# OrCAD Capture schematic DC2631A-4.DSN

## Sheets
1 PAGE3: size A
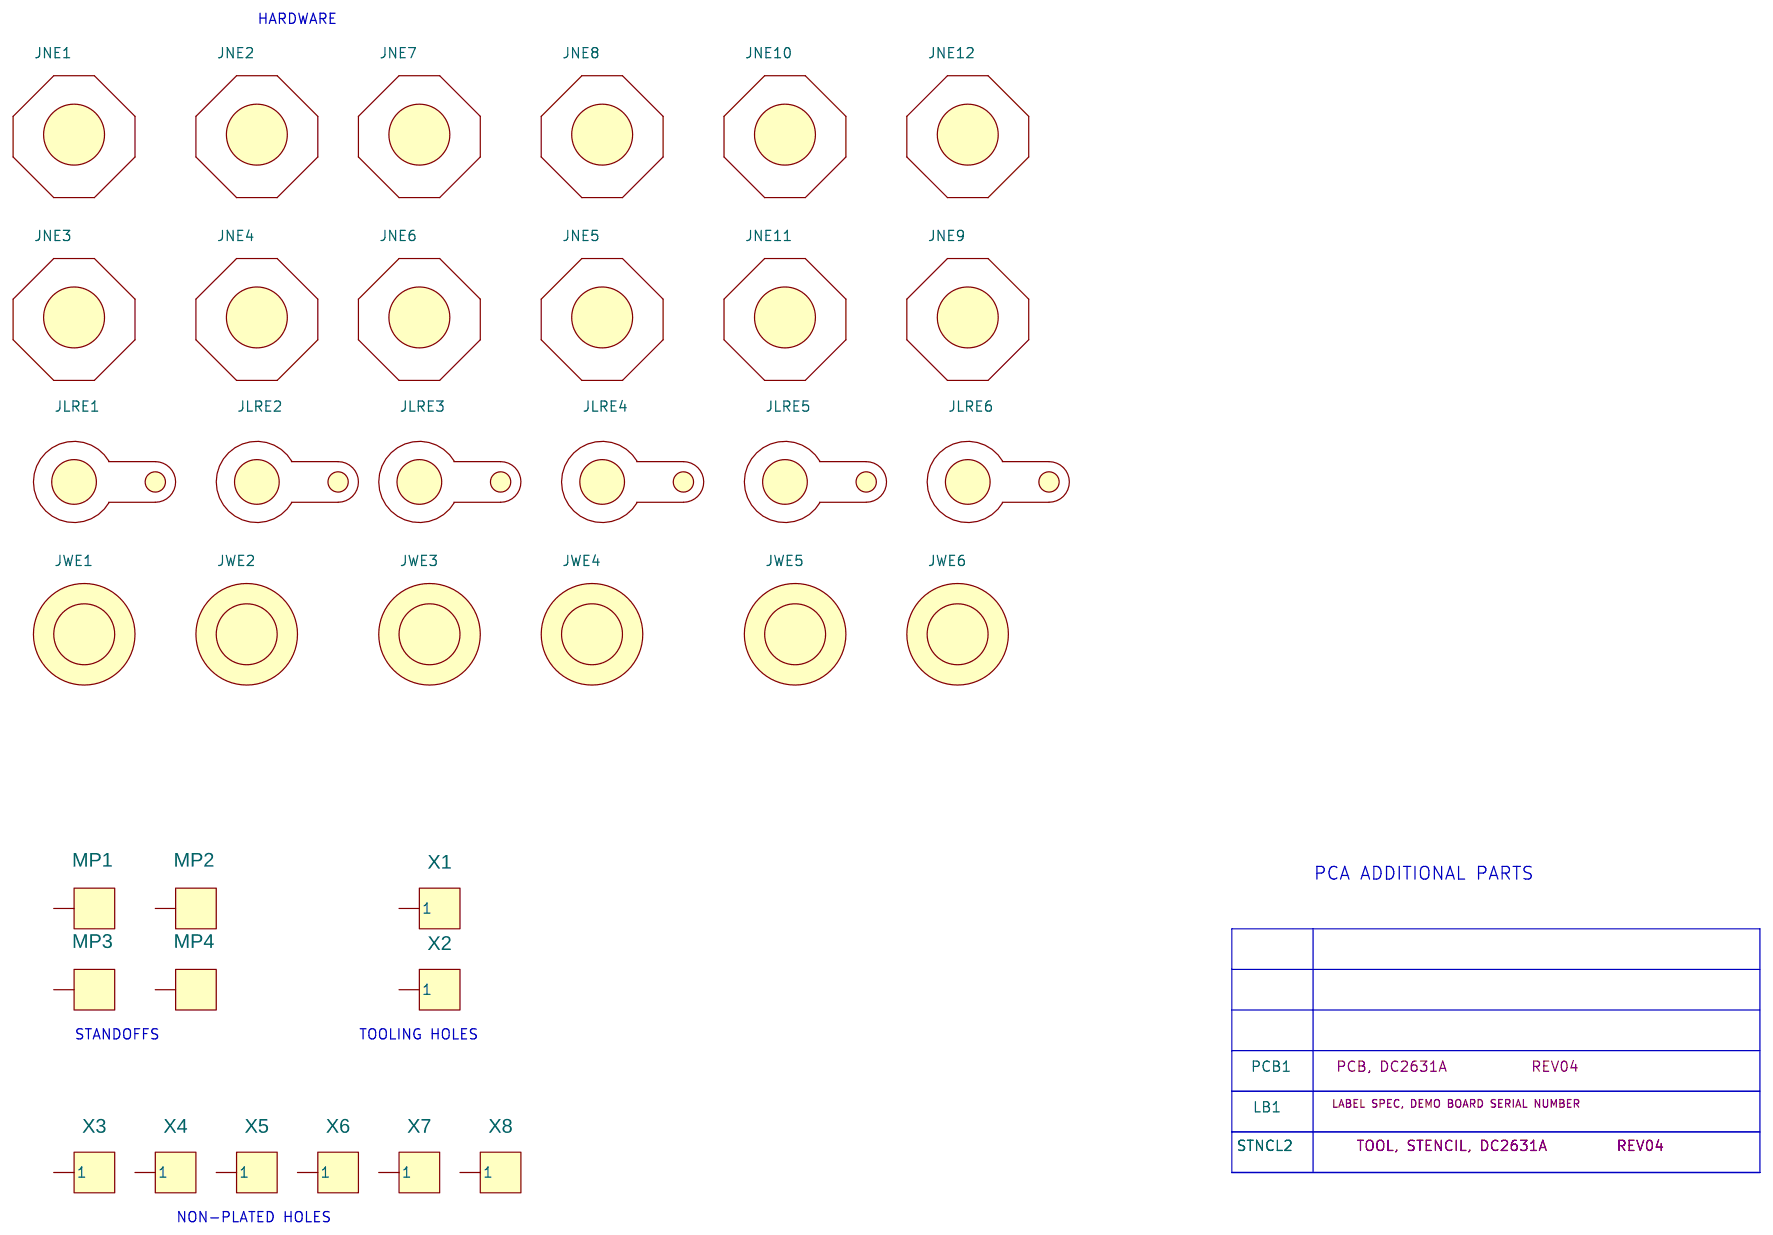
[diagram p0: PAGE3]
2 PAGE1: size Custom; company: ANALOG DEVICES; note: DEMO BOARD BILL OF MATERIALS; note: HIGH EFFICIENCY 6  PHASE STEP-DOWN CONVERTER
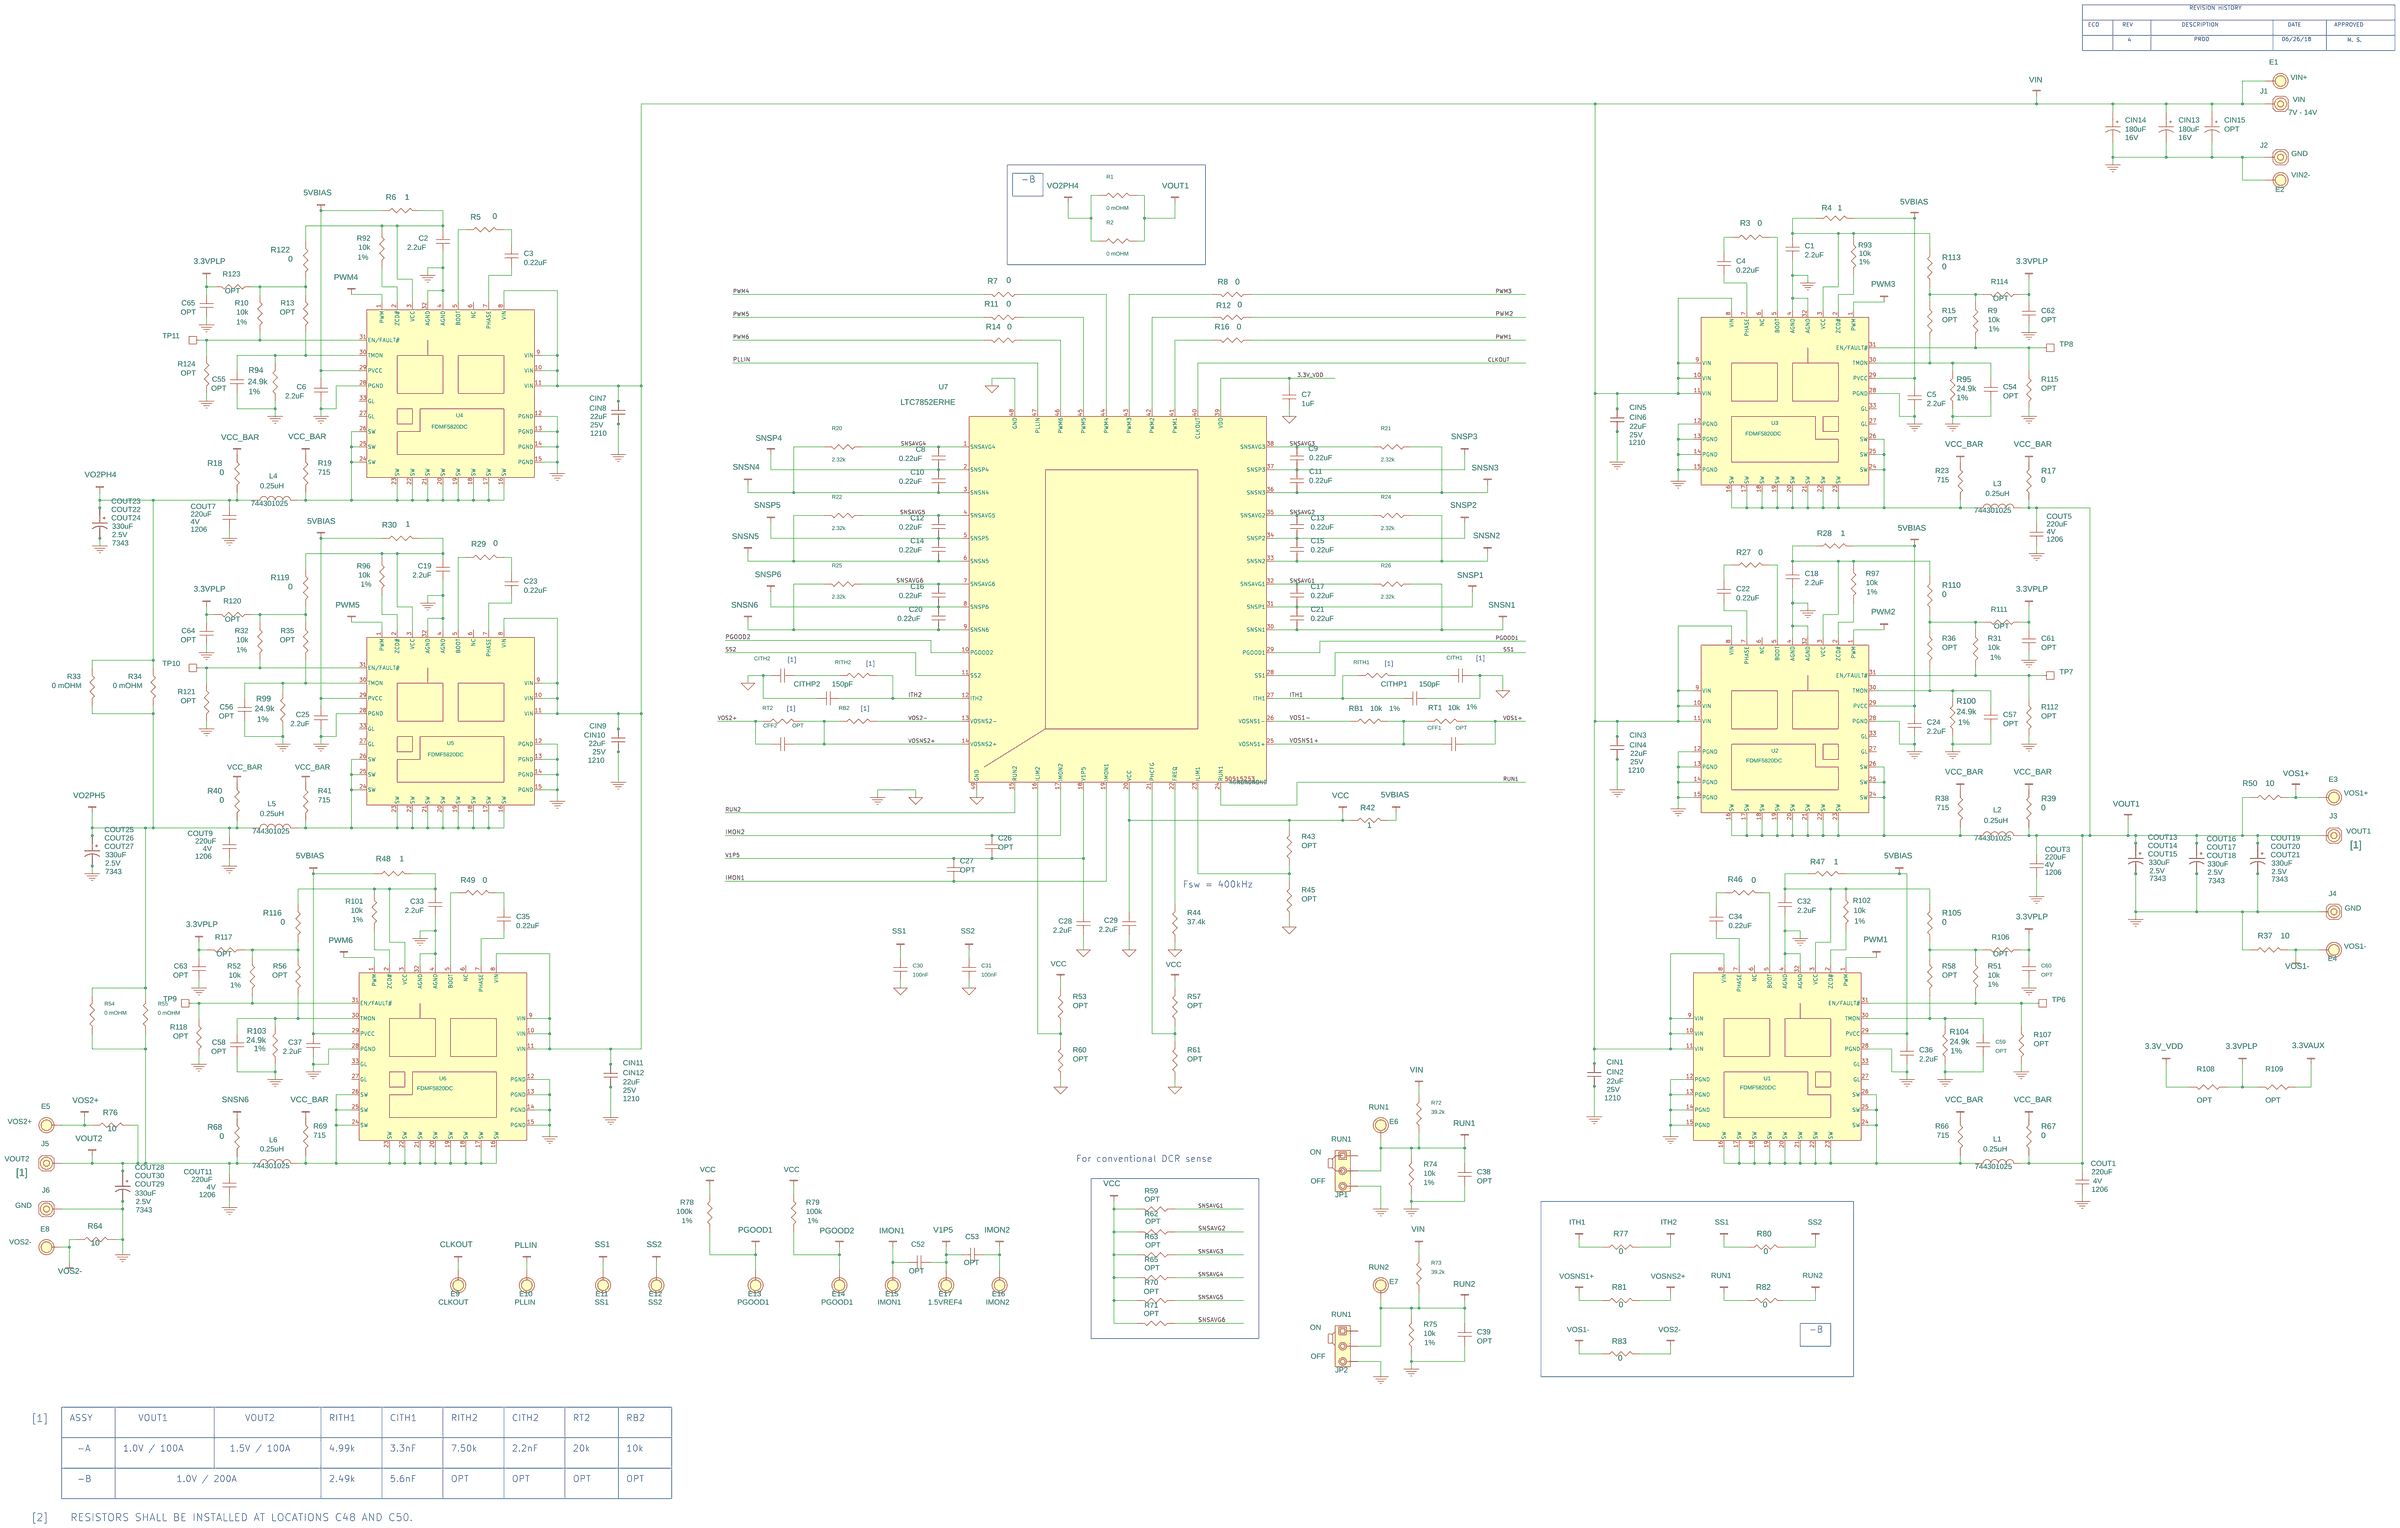
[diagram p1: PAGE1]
3 PAGE2: size Custom; company: ANALOG DEVICES; note: DEMO BOARD BILL OF MATERIALS; note: HIGH EFFICIENCY 6  PHASE STEP-DOWN CONVERTER
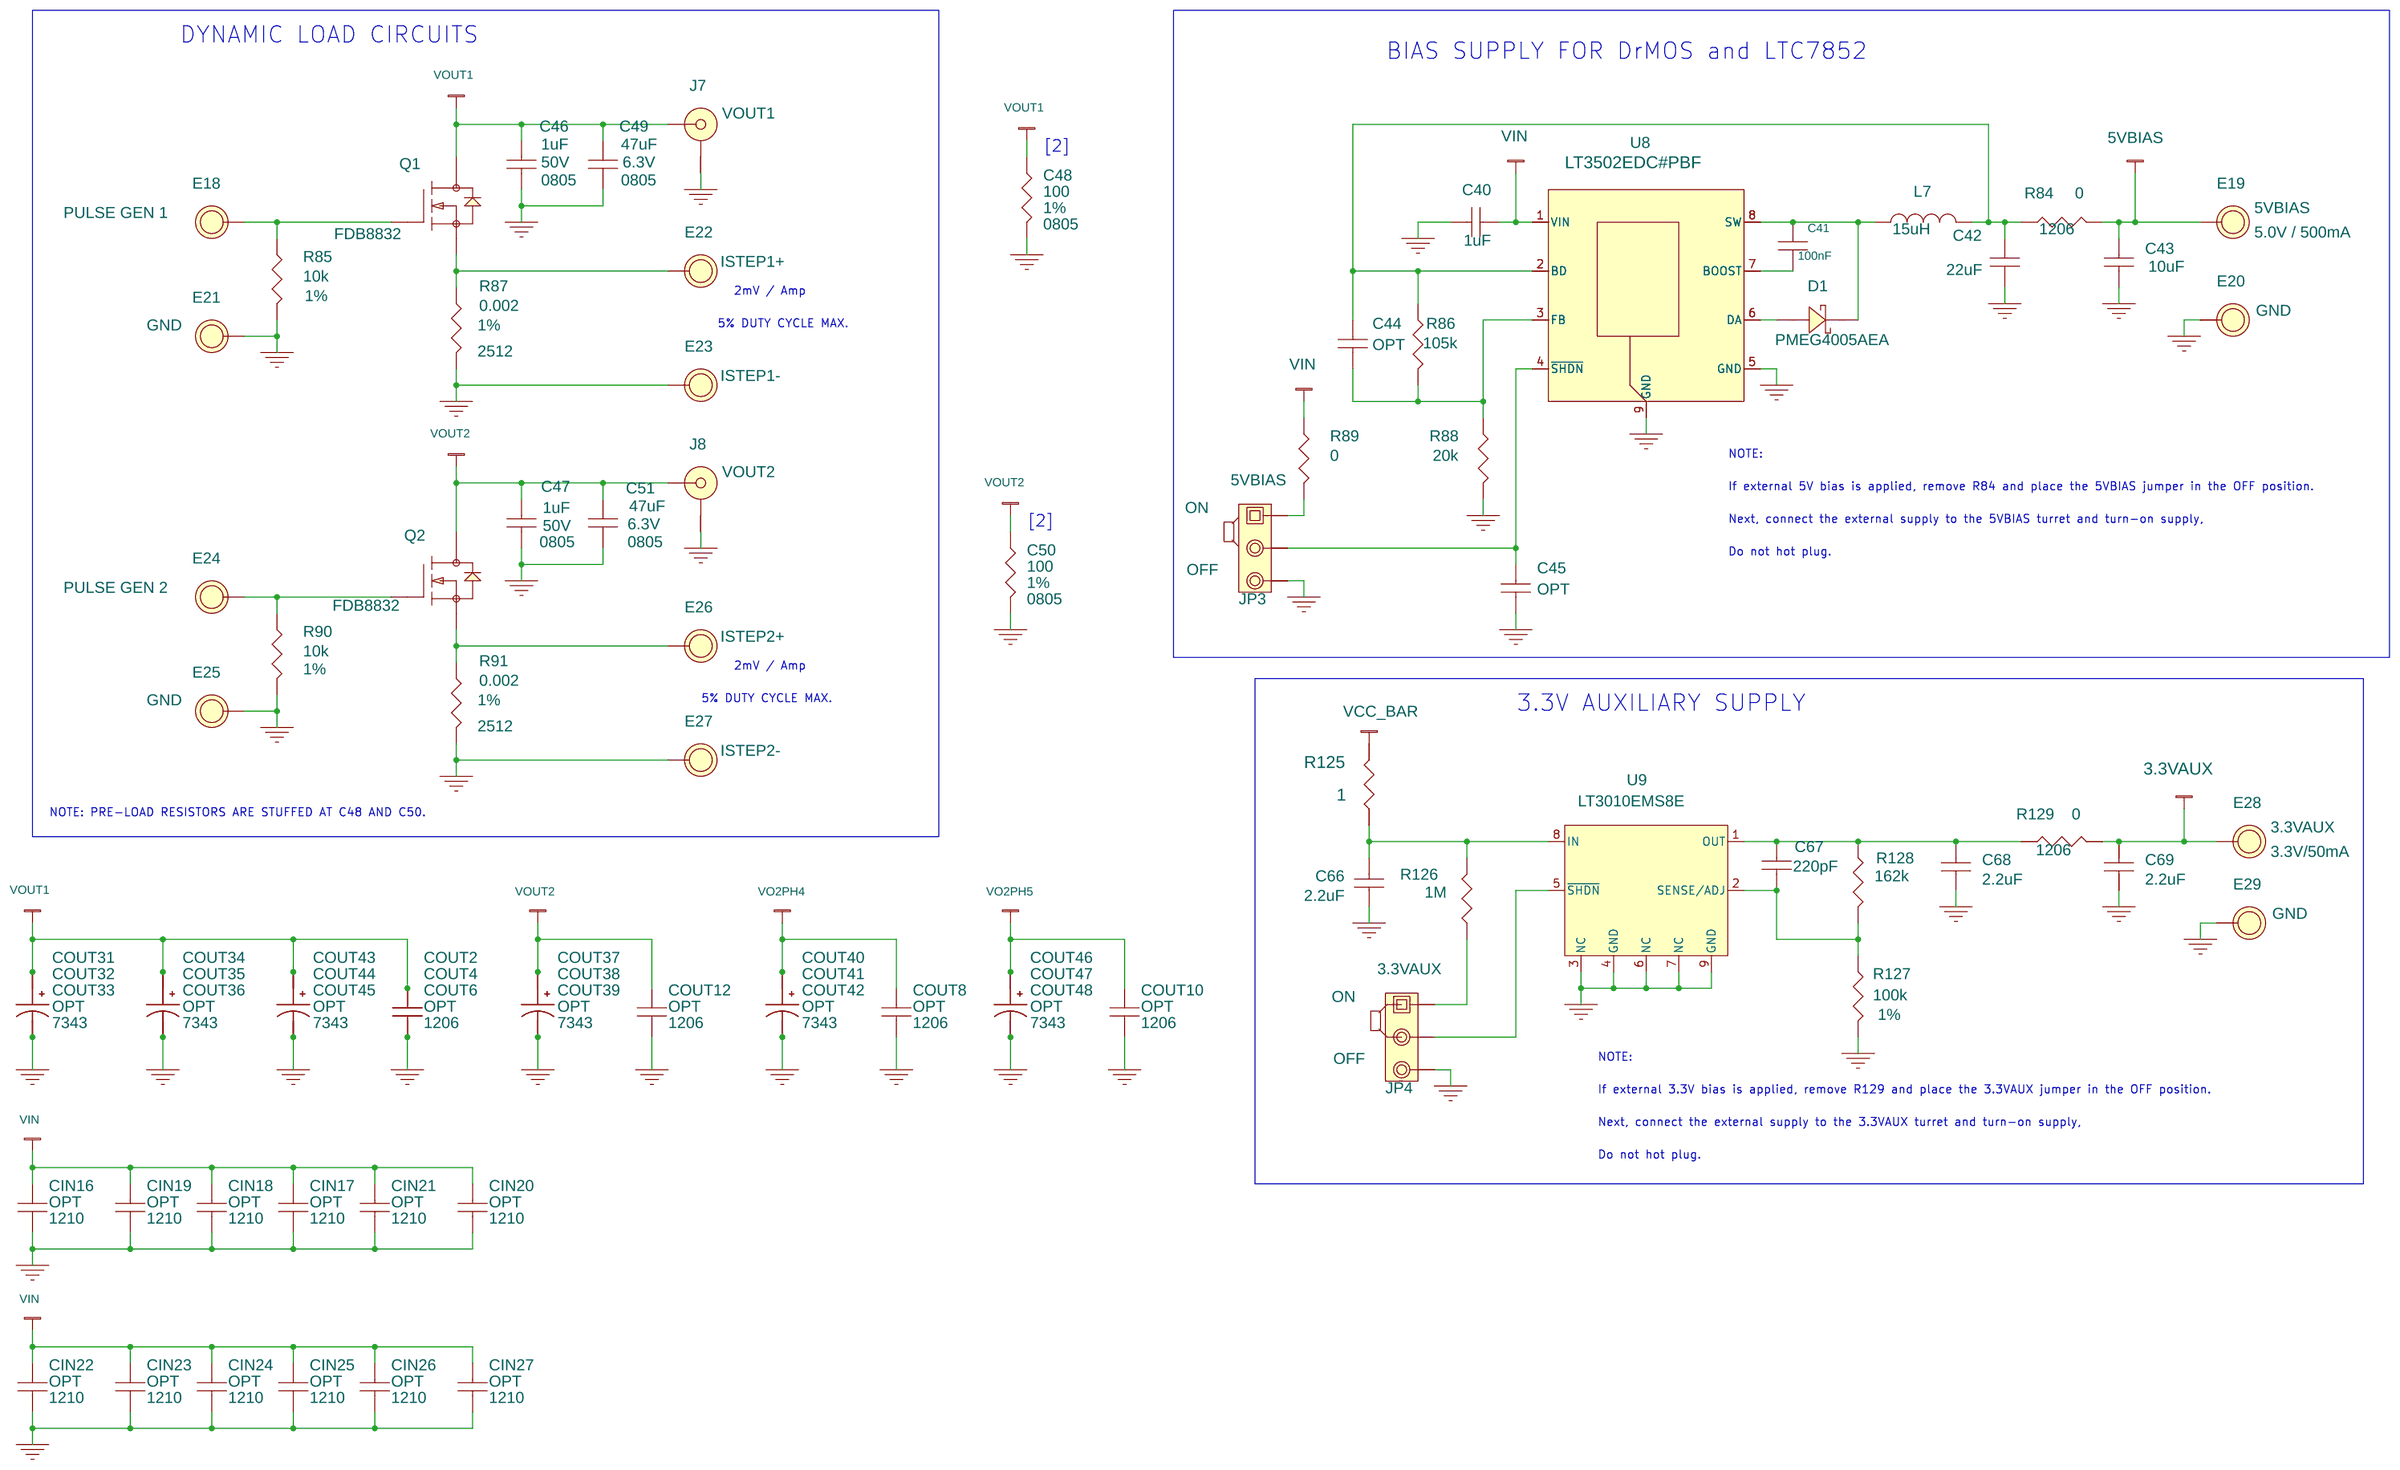
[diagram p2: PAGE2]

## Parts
sheet PAGE1
C1  2.2uF  [CC0603N]
C2  2.2uF  [CC0603N]
C3  0.22uF  [CC0603N]
C4  0.22uF  [CC0603N]
C5  2.2uF  [CC0603N]
C6  2.2uF  [CC0603N]
C7  1uF  [CC0603N]
C8  0.22uF  [CC0603N]
C9  0.22uF  [CC0603N]
C10  0.22uF  [CC0603N]
C11  0.22uF  [CC0603N]
C12  0.22uF  [CC0603N]
C13  0.22uF  [CC0603N]
C14  0.22uF  [CC0603N]
C15  0.22uF  [CC0603N]
C16  0.22uF  [CC0603N]
C17  0.22uF  [CC0603N]
C18  2.2uF  [CC0603N]
C19  2.2uF  [CC0603N]
C20  0.22uF  [CC0603N]
C21  0.22uF  [CC0603N]
C22  0.22uF  [CC0603N]
C23  0.22uF  [CC0603N]
C24  2.2uF  [CC0603N]
C25  2.2uF  [CC0603N]
C26  OPT  [CC0603N]
C27  OPT  [CC0603N]
C28  2.2uF  [CC0603N]
C29  2.2uF  [CC0603N]
C30  100nF  [CC0603N]
C31  100nF  [CC0603N]
C32  2.2uF  [CC0603N]
C33  2.2uF  [CC0603N]
C34  0.22uF  [CC0603N]
C35  0.22uF  [CC0603N]
C36  2.2uF  [CC0603N]
C37  2.2uF  [CC0603N]
C38  OPT  [CC0603N]
C39  OPT  [CC0603N]
C52  OPT  [CC0603N]
C53  OPT  [CC0603N]
C54  OPT  [CC0603N]
C55  OPT  [CC0603N]
C56  OPT  [CC0603N]
C57  OPT  [CC0603N]
C58  OPT  [CC0603N]
C59  OPT  [CC0603N]
C60  OPT  [CC0603N]
C61  OPT  [CC0603N]
C62  OPT  [CC0603N]
C63  OPT  [CC0603N]
C64  OPT  [CC0603N]
C65  OPT  [CC0603N]
CFF1  OPT  [CC0603N]
CFF2  OPT  [CC0603N]
CIN1  22uF  [CC1210N]
CIN2  22uF  [CC1210N]
CIN3  22uF  [CC1210N]
CIN4  22uF  [CC1210N]
CIN5  22uF  [CC1210N]
CIN6  22uF  [CC1210N]
CIN7  22uF  [CC1210N]
CIN8  22uF  [CC1210N]
CIN9  22uF  [CC1210N]
CIN10  22uF  [CC1210N]
CIN11  22uF  [CC1210N]
CIN12  22uF  [CC1210N]
CIN13  180uF  [CAP\SANYO\SVP\F8\10.3X10.3]
CIN14  180uF  [CAP\SANYO\SVP\F8\10.3X10.3]
CIN15  OPT  [CAP\SANYO\SVP\F8\10.3X10.3]
CITH1  3300pF  [CC0603N]
CITH2  2200pF  [CC0603N]
CITHP1  150pF  [CC0603N]
CITHP2  150pF  [CC0603N]
COUT1  220uF  [CC1206N]
COUT3  220uF  [CC1206N]
COUT5  220uF  [CC1206N]
COUT7  220uF  [CC1206N]
COUT9  220uF  [CC1206N]
COUT11  220uF  [CC1206N]
COUT13  330uF  [CAPMP7343N]
COUT14  330uF  [CAPMP7343N]
COUT15  330uF  [CAPMP7343N]
COUT16  330uF  [CAPMP7343N]
COUT17  330uF  [CAPMP7343N]
COUT18  330uF  [CAPMP7343N]
COUT19  330uF  [CAPMP7343N]
COUT20  330uF  [CAPMP7343N]
COUT21  330uF  [CAPMP7343N]
COUT22  330uF  [CAPMP7343N]
COUT23  330uF  [CAPMP7343N]
COUT24  330uF  [CAPMP7343N]
COUT25  330uF  [CAPMP7343N]
COUT26  330uF  [CAPMP7343N]
COUT27  330uF  [CAPMP7343N]
COUT28  330uF  [CAPMP7343N]
COUT29  330uF  [CAPMP7343N]
COUT30  330uF  [CAPMP7343N]
E1  TEST POINT  [MM/2501]
E2  TEST POINT  [MM/2501]
E3  TEST POINT  [MM/2501]
E4  TEST POINT  [MM/2501]
E5  TEST POINT  [MM/2501]
E6  TEST POINT  [MM/2501]
E7  TEST POINT  [MM/2501]
E8  TEST POINT  [MM/2501]
E9  TEST POINT  [MM/2501]
E10  TEST POINT  [MM/2501]
E11  TEST POINT  [MM/2501]
E12  TEST POINT  [MM/2501]
E13  TEST POINT  [MM/2501]
E14  TEST POINT  [MM/2501]
E15  TEST POINT  [MM/2501]
E16  TEST POINT  [MM/2501]
E17  TEST POINT  [MM/2501]
J1  STUD, FASTENER, #10-32  [PENN-KFH-032]
J2  STUD, FASTENER, #10-32  [PENN-KFH-032]
J3  STUD, FASTENER, #10-32  [PENN-KFH-032]
J4  STUD, FASTENER, #10-32  [PENN-KFH-032]
J5  STUD, FASTENER, #10-32  [PENN-KFH-032]
J6  STUD, FASTENER, #10-32  [PENN-KFH-032]
JP1  HDR  [HD1X3-079]
JP2  HDR  [HD1X3-079]
L1  0.25uH  [IND\WURTH\7443010XX]
L2  0.25uH  [IND\WURTH\7443010XX]
L3  0.25uH  [IND\WURTH\7443010XX]
L4  0.25uH  [IND\WURTH\7443010XX]
L5  0.25uH  [IND\WURTH\7443010XX]
L6  0.25uH  [IND\WURTH\7443010XX]
R1  0 mOHM  [RN6083_2010]
R2  0 mOHM  [RN6083_2010]
R3  0  [CR0603N]
R4  1  [CR0603N]
R5  0  [CR0603N]
R6  1  [CR0603N]
R7  0  [CR0603N]
R8  0  [CR0603N]
R9  10k  [CR0603N]
R10  10k  [CR0603N]
R11  0  [CR0603N]
R12  0  [CR0603N]
R13  OPT  [CR0603N]
R14  0  [CR0603N]
R15  OPT  [CR0603N]
R16  0  [CR0603N]
R17  0  [CR0603N]
R18  0  [CR0603N]
R19  715  [CR0603N]
R20  2.32k  [CR0603N]
R21  2.32k  [CR0603N]
R22  2.32k  [CR0603N]
R23  715  [CR0603N]
R24  2.32k  [CR0603N]
R25  2.32k  [CR0603N]
R26  2.32k  [CR0603N]
R27  0  [CR0603N]
R28  1  [CR0603N]
R29  0  [CR0603N]
R30  1  [CR0603N]
R31  10k  [CR0603N]
R32  10k  [CR0603N]
R33  0 mOHM  [RN6083_2010]
R34  0 mOHM  [RN6083_2010]
R35  OPT  [CR0603N]
R36  OPT  [CR0603N]
R37  10  [CR0603N]
R38  715  [CR0603N]
R39  0  [CR0603N]
R40  0  [CR0603N]
R41  715  [CR0603N]
R42  1  [CR0603N]
R43  OPT  [CR0603N]
R44  37.4k  [CR0603N]
R45  OPT  [CR0603N]
R46  0  [CR0603N]
R47  1  [CR0603N]
R48  1  [CR0603N]
R49  0  [CR0603N]
R50  10  [CR0603N]
R51  10k  [CR0603N]
R52  10k  [CR0603N]
R53  OPT  [CR0603N]
R54  0 mOHM  [RN6083_2010]
R55  0 mOHM  [RN6083_2010]
R56  OPT  [CR0603N]
R57  OPT  [CR0603N]
R58  OPT  [CR0603N]
R59  OPT  [CR0603N]
R60  OPT  [CR0603N]
R61  OPT  [CR0603N]
R62  OPT  [CR0603N]
R63  OPT  [CR0603N]
R64  10  [CR0603N]
R65  OPT  [CR0603N]
R66  715  [CR0603N]
R67  0  [CR0603N]
R68  0  [CR0603N]
R69  715  [CR0603N]
R70  OPT  [CR0603N]
R71  OPT  [CR0603N]
R72  39.2k  [CR0603N]
R73  39.2k  [CR0603N]
R74  10k  [CR0603N]
R75  10k  [CR0603N]
R76  10  [CR0603N]
R77  0  [CR0603N]
R78  100k  [CR0603N]
R79  100k  [CR0603N]
R80  0  [CR0603N]
R81  0  [CR0603N]
R82  0  [CR0603N]
R83  0  [CR0603N]
R92  10k  [CR0603N]
R93  10k  [CR0603N]
R94  24.9k  [CR0603N]
R95  24.9k  [CR0603N]
R96  10k  [CR0603N]
R97  10k  [CR0603N]
R99  24.9k  [CR0603N]
R100  24.9k  [CR0603N]
R101  10k  [CR0603N]
R102  10k  [CR0603N]
R103  24.9k  [CR0603N]
R104  24.9k  [CR0603N]
R105  0  [CR0603N]
R106  OPT  [CR0603N]
R107  OPT  [CR0603N]
R108  OPT  [CR0603N]
R109  OPT  [CR0603N]
R110  0  [CR0603N]
R111  OPT  [CR0603N]
R112  OPT  [CR0603N]
R113  0  [CR0603N]
R114  OPT  [CR0603N]
R115  OPT  [CR0603N]
R116  0  [CR0603N]
R117  OPT  [CR0603N]
R118  OPT  [CR0603N]
R119  0  [CR0603N]
R120  OPT  [CR0603N]
R121  OPT  [CR0603N]
R122  0  [CR0603N]
R123  OPT  [CR0603N]
R124  OPT  [CR0603N]
RB1  10k  [CR0603N]
RB2  10k  [CR0603N]
RITH1  4.99k  [CR0603N]
RITH2  7.5k  [CR0603N]
RT1  10k  [CR0603N]
RT2  20k  [CR0603N]
TP6  CLKOUT34  [TEST-PADS]
TP7  CLKOUT34  [TEST-PADS]
TP8  CLKOUT34  [TEST-PADS]
TP9  CLKOUT34  [TEST-PADS]
TP10  CLKOUT34  [TEST-PADS]
TP11  CLKOUT34  [TEST-PADS]
U1  FDMF5820DC  [fAIRCHILD-FDMF5820DC]
U2  FDMF5820DC  [fAIRCHILD-FDMF5820DC]
U3  FDMF5820DC  [fAIRCHILD-FDMF5820DC]
U4  FDMF5820DC  [fAIRCHILD-FDMF5820DC]
U5  FDMF5820DC  [fAIRCHILD-FDMF5820DC]
U6  FDMF5820DC  [fAIRCHILD-FDMF5820DC]
U7  LTC7852ERHE  [LTC-RHE-48-1527]
XJP1  SHUNT
XJP2  SHUNT
sheet PAGE2
C40  1uF  [CC0805N]
C41  100nF  [CC0603N]
C42  22uF  [CC0805N]
C43  10uF  [CC0805N]
C44  OPT  [CC0603N]
C45  OPT  [CC0603N]
C46  1uF  [CC0805N]
C47  1uF  [CC0805N]
C48  100  [CR0805N]
C49  47uF  [CC0805N]
C50  100  [CR0805N]
C51  47uF  [CC0805N]
C66  2.2uF  [CC0603N]
C67  220pF  [CC0603N]
C68  2.2uF  [CC0603N]
C69  2.2uF  [CC0603N]
CIN16  OPT  [CC1210N]
CIN17  OPT  [CC1210N]
CIN18  OPT  [CC1210N]
CIN19  OPT  [CC1210N]
CIN20  OPT  [CC1210N]
CIN21  OPT  [CC1210N]
CIN22  OPT  [CC1210N]
CIN23  OPT  [CC1210N]
CIN24  OPT  [CC1210N]
CIN25  OPT  [CC1210N]
CIN26  OPT  [CC1210N]
CIN27  OPT  [CC1210N]
COUT2  OPT  [CC1206N]
COUT4  OPT  [CC1206N]
COUT6  OPT  [CC1206N]
COUT8  OPT  [CC1206N]
COUT10  OPT  [CC1206N]
COUT12  OPT  [CC1206N]
COUT31  OPT  [CAPMP7343N]
COUT32  OPT  [CAPMP7343N]
COUT33  OPT  [CAPMP7343N]
COUT34  OPT  [CAPMP7343N]
COUT35  OPT  [CAPMP7343N]
COUT36  OPT  [CAPMP7343N]
COUT37  OPT  [CAPMP7343N]
COUT38  OPT  [CAPMP7343N]
COUT39  OPT  [CAPMP7343N]
COUT40  OPT  [CAPMP7343N]
COUT41  OPT  [CAPMP7343N]
COUT42  OPT  [CAPMP7343N]
COUT43  OPT  [CAPMP7343N]
COUT44  OPT  [CAPMP7343N]
COUT45  OPT  [CAPMP7343N]
COUT46  OPT  [CAPMP7343N]
COUT47  OPT  [CAPMP7343N]
COUT48  OPT  [CAPMP7343N]
D1  PMEG4005AEA  [SOD323]
E18  TEST POINT  [MM/2501]
E19  TEST POINT  [MM/2501]
E20  TEST POINT  [MM/2501]
E21  TEST POINT  [MM/2501]
E22  TEST POINT  [MM/2501]
E23  TEST POINT  [MM/2501]
E24  TEST POINT  [MM/2501]
E25  TEST POINT  [MM/2501]
E26  TEST POINT  [MM/2501]
E27  TEST POINT  [MM/2501]
E28  TEST POINT  [MM/2501]
E29  TEST POINT  [MM/2501]
J7  RF, BNC  [BNC5]
J8  RF, BNC  [BNC5]
JP3  HDR  [HD1X3-079]
JP4  HDR  [HD1X3-079]
L7  15uH  [IND\EATON\MP140-V2]
Q1  FDB8832  [TO-263AB]
Q2  FDB8832  [TO-263AB]
R84  0  [CR1206N]
R85  10k  [CR0603N]
R86  105k  [CR0603N]
R87  0.002  [CR2512N]
R88  20k  [CR0603N]
R89  0  [CR0603N]
R90  10k  [CR0603N]
R91  0.002  [CR2512N]
R125  1  [CR0603N]
R126  1M  [CR0603N]
R127  100k  [CR0603N]
R128  162k  [CR0603N]
R129  0  [CR1206N]
U8  LT3502EDC#PBF  [LTC-DC8-8-1719]
U9  LT3010EMS8E  [LTC-MS8E-8-1662]
XJP3  SHUNT
XJP4  SHUNT
sheet PAGE3
JLRE1  Lug_Ring
JLRE2  Lug_Ring
JLRE3  Lug_Ring
JLRE4  Lug_Ring
JLRE5  Lug_Ring
JLRE6  Lug_Ring
JNE1  NUT
JNE2  NUT
JNE3  NUT
JNE4  NUT
JNE5  NUT
JNE6  NUT
JNE7  NUT
JNE8  NUT
JNE9  NUT
JNE10  NUT
JNE11  NUT
JNE12  NUT
JWE1  Washer
JWE2  Washer
JWE3  Washer
JWE4  Washer
JWE5  Washer
JWE6  Washer
LB1  LABEL  [895-0154_REV01]
MP1  STANDOFF  [KEYSTONE_8829-8834]
MP2  STANDOFF  [KEYSTONE_8829-8834]
MP3  STANDOFF  [KEYSTONE_8829-8834]
MP4  STANDOFF  [KEYSTONE_8829-8834]
PCB1  PCB, DC2631A
STNCL1  TOOL, STENCIL, 700-DC2631A
STNCL2  TOOL, STENCIL, 700-DC2631A
X1  CON1  [TOOL\ALGNHL\70]
X2  CON1  [TOOL\ALGNHL\70]
X3  CON1  [RP40\20]
X4  CON1  [RP40\20]
X5  CON1  [RP40\20]
X6  CON1  [RP40\20]
X7  CON1  [RP40\20]
X8  CON1  [RP40\20]

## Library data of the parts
C1 C2 C5 C6 C18 C19 C24 C25 C28 C29 C32 C33 C36 C37 C66 C68 C69 = CAP: CAP.,2.2uF,X5R,16V,10%,0603; CLASS: DISCRETE; Dielectric Type: X5R; FPLIST: CC0603N,CC0603L,CC0603M; Manufacturer: KEMET; Manufacturer PN: C0603C225K4PAC7867; PART_NUMBER: 150-0552; Package Size: 0603; Rated Voltage: 16V; Tolerance: 10%
C3 C4 C8-C17 C20-C23 C34 C35 = CAP: CAP.,0.22uF,X5R,25V,10%,0603; CLASS: DISCRETE; Dielectric Type: X5R; FPLIST: CC0603N,CC0603L,CC0603M; Manufacturer: AVX; Manufacturer PN: 06033D224KAT2A; PART_NUMBER: 150-3369; Package Size: 0603; Rated Voltage: 25V; Tolerance: 10%
C7 = CAP: CAP.,1uF,X5R,25V,20%,0603; CLASS: DISCRETE; Dielectric Type: X5R; FPLIST: CC0603N,CC0603L,CC0603M; Manufacturer: AVX; Manufacturer PN: 06033D105MAT2A; PART_NUMBER: 150-0187; Package Size: 0603; Rated Voltage: 25V; Tolerance: 20%
C26 C27 C38 C39 C52-C65 = CAP: CAP., OPTION, 0603; CLASS: DISCRETE; FPLIST: CC0603N,CC0603L,CC0603M; PART_NUMBER: 150-3038; Package Size: 0603; Package Type: SMD
C30 C31 C41 = CAP: CAP.,0.1uF,X7R,16V,5%,0603; CLASS: DISCRETE; Dielectric Type: X7R; FPLIST: CC0603N,CC0603L,CC0603M; Manufacturer: AVX; Manufacturer PN: 0603YC104JAT2A; PART_NUMBER: 150-3212; Package Size: 0603; Rated Voltage: 16V; Tolerance: 5%
C44 C45 CFF1 CFF2 = CAP: CAP., OPTION, 0603; CLASS: DISCRETE; FPLIST: CC0603N,CC0603L,CC0603M; PART_NUMBER: 150-3038; Package Size: 0603; Package Type: SMD; Part Number: OPTION
CIN1-CIN12 = CAP: CAP.,22uF,X5R,25V,10%,1210; CLASS: DISCRETE; Dielectric Type: X5R; FPLIST: CC1210N,CC1210L,CC1210M; Manufacturer: MURATA; Manufacturer PN: GRM32ER61E226KE15L; PART_NUMBER: 150-3033; Package Size: 1210; Package Type: SMD; Rated Voltage: 25V; Tolerance: 10%
CIN13 CIN14 = CAP_P: CAP.,180uF,ALUM. POLYMER,16V,20%,SMD; CLASS: DISCRETE; Dielectric Type: ALUM. POLYMER; Manufacturer: PANASONIC; Manufacturer PN: 16SVP180MX; PART_NUMBER: TMP-2446; Package Size: SMD; Rated Voltage: 16V; Tolerance: 20%
CIN15 = CAP_P: CAP.,OPTION,ALUM. ELECT.,SMD; CLASS: DISCRETE; PART_NUMBER: 150-3571; Package Type: SMD
CITH1 = CAP: CAP.,3300pF,X7R,50V,10%,0603; CLASS: DISCRETE; Dielectric Type: X7R; FPLIST: CC0603N,CC0603L,CC0603M; Manufacturer: AVX; Manufacturer PN: 06035C332KAT2A; PART_NUMBER: 150-3071; Package Size: 0603; Rated Voltage: 50V; Tolerance: 10%
CITH2 = CAP: CAP.,2200pF,C0G,50V,5%,0603; CLASS: DISCRETE; FPLIST: CC0603N,CC0603L,CC0603M; PART_NUMBER: 150-0572; Package Size: 0603
CITHP1 CITHP2 = CAP: CAP.,150pF,NP0,50V,5%,0603; CLASS: DISCRETE; Dielectric Type: NP0; FPLIST: CC0603N,CC0603L,CC0603M; Manufacturer: AVX; Manufacturer PN: 06035A151JAT2A; PART_NUMBER: 150-2306; Package Size: 0603; Rated Voltage: 50V; Tolerance: 5%
COUT1 COUT3 COUT5 COUT7 COUT9 COUT11 = CAP: CAP.,220uF,X5R,4V,20%,1206,NO SUBS. ALLOWED; CLASS: DISCRETE; Dielectric Type: X5R; FPLIST: CC1206N,CC1206L,CC1206M; Manufacturer: MURATA; Manufacturer PN: GRM31CR60G227ME11L; PART_NUMBER: 150-3323; Package Size: 1206; Rated Voltage: 4V; Tolerance: 20%
COUT13-COUT30 = CAP_P: CAP.,330uF,ALUM. ELECT.,2.5V,20%,7343,9mOhms, 6.3A; CLASS: DISCRETE; Dielectric Type: ALUM. ELECT.; FPLIST: CAPMP7343N,CAPMP7343L,CAPMP7343M; Manufacturer: PANASONIC; Manufacturer PN: EEFSX0E331ER; PART_NUMBER: 150-2330; Package Size: 7343; Rated Voltage: 2.5V; Tolerance: 20%
E1 = TURRET_A: TEST POINT,TURRET,0.094",MTG. HOLE; 9th Part Field: VIN+; CLASS: IO; Manufacturer: MILL-MAX; Manufacturer PN: 2501-2-00-80-00-00-07-0; PART_FIELD_01: <PART_FIELD_01>; PART_NUMBER: 260-0003
E2 = TURRET_A: TEST POINT,TURRET,0.094",MTG. HOLE; 9th Part Field: VIN2-; CLASS: IO; Manufacturer: MILL-MAX; Manufacturer PN: 2501-2-00-80-00-00-07-0; PART_FIELD_01: <PART_FIELD_01>; PART_NUMBER: 260-0003
E3 = TURRET_A: TEST POINT,TURRET,0.094",MTG. HOLE; 9th Part Field: VOS1+; CLASS: IO; Manufacturer: MILL-MAX; Manufacturer PN: 2501-2-00-80-00-00-07-0; PART_FIELD_01: <PART_FIELD_01>; PART_NUMBER: 260-0003
E4 = TURRET_A: TEST POINT,TURRET,0.094",MTG. HOLE; 9th Part Field: VOS1-; CLASS: IO; Manufacturer: MILL-MAX; Manufacturer PN: 2501-2-00-80-00-00-07-0; PART_FIELD_01: <PART_FIELD_01>; PART_NUMBER: 260-0003
E5 = TURRET_A: TEST POINT,TURRET,0.094",MTG. HOLE; 9th Part Field: VOS2+; CLASS: IO; Manufacturer: MILL-MAX; Manufacturer PN: 2501-2-00-80-00-00-07-0; PART_FIELD_01: <PART_FIELD_01>; PART_NUMBER: 260-0003
E6 = TURRET_A: TEST POINT,TURRET,0.094",MTG. HOLE; 9th Part Field: RUN1; CLASS: IO; Manufacturer: MILL-MAX; Manufacturer PN: 2501-2-00-80-00-00-07-0; PART_FIELD_01: <PART_FIELD_01>; PART_NUMBER: 260-0003
E7 = TURRET_A: TEST POINT,TURRET,0.094",MTG. HOLE; 9th Part Field: RUN2; CLASS: IO; Manufacturer: MILL-MAX; Manufacturer PN: 2501-2-00-80-00-00-07-0; PART_FIELD_01: <PART_FIELD_01>; PART_NUMBER: 260-0003
E8 = TURRET_A: TEST POINT,TURRET,0.094",MTG. HOLE; 9th Part Field: VOS2-; CLASS: IO; Manufacturer: MILL-MAX; Manufacturer PN: 2501-2-00-80-00-00-07-0; PART_FIELD_01: <PART_FIELD_01>; PART_NUMBER: 260-0003
E9 = TURRET_A: TEST POINT,TURRET,0.094",MTG. HOLE; 9th Part Field: CLKOUT; CLASS: IO; Manufacturer: MILL-MAX; Manufacturer PN: 2501-2-00-80-00-00-07-0; PART_FIELD_01: <PART_FIELD_01>; PART_NUMBER: 260-0003
E10 = TURRET_A: TEST POINT,TURRET,0.094",MTG. HOLE; 9th Part Field: PLLIN; CLASS: IO; Manufacturer: MILL-MAX; Manufacturer PN: 2501-2-00-80-00-00-07-0; PART_FIELD_01: <PART_FIELD_01>; PART_NUMBER: 260-0003
E11 = TURRET_A: TEST POINT,TURRET,0.094",MTG. HOLE; 9th Part Field: SS1; CLASS: IO; Manufacturer: MILL-MAX; Manufacturer PN: 2501-2-00-80-00-00-07-0; PART_FIELD_01: <PART_FIELD_01>; PART_NUMBER: 260-0003
E12 = TURRET_A: TEST POINT,TURRET,0.094",MTG. HOLE; 9th Part Field: SS2; CLASS: IO; Manufacturer: MILL-MAX; Manufacturer PN: 2501-2-00-80-00-00-07-0; PART_FIELD_01: <PART_FIELD_01>; PART_NUMBER: 260-0003
E13 E14 = TURRET_A: TEST POINT,TURRET,0.094",MTG. HOLE; 9th Part Field: PGOOD1; CLASS: IO; Manufacturer: MILL-MAX; Manufacturer PN: 2501-2-00-80-00-00-07-0; PART_FIELD_01: <PART_FIELD_01>; PART_NUMBER: 260-0003
E15 = TURRET_A: TEST POINT,TURRET,0.094",MTG. HOLE; 9th Part Field: IMON1; CLASS: IO; Manufacturer: MILL-MAX; Manufacturer PN: 2501-2-00-80-00-00-07-0; PART_FIELD_01: <PART_FIELD_01>; PART_NUMBER: 260-0003
E16 = TURRET_A: TEST POINT,TURRET,0.094",MTG. HOLE; 9th Part Field: IMON2; CLASS: IO; Manufacturer: MILL-MAX; Manufacturer PN: 2501-2-00-80-00-00-07-0; PART_FIELD_01: <PART_FIELD_01>; PART_NUMBER: 260-0003
E17 = TURRET_A: TEST POINT,TURRET,0.094",MTG. HOLE; 9th Part Field: 1.5VREF4; CLASS: IO; Manufacturer: MILL-MAX; Manufacturer PN: 2501-2-00-80-00-00-07-0; PART_FIELD_01: <PART_FIELD_01>; PART_NUMBER: 260-0003
J1 = PEM-KFH: 10th Part Field: 7V - 14V; 9th Part Field: VIN; CLASS: DISCRETE; Manufacturer: PENNENGINEERING; Manufacturer PN: KFH-032-10ET; PART_NUMBER: 769-0005
J2 J4 J6 = PEM-KFH: 9th Part Field: GND; CLASS: DISCRETE; Manufacturer: PENNENGINEERING; Manufacturer PN: KFH-032-10ET; PART_NUMBER: 769-0005
J3 = PEM-KFH: 10th Part Field: [1]; 9th Part Field: VOUT1; CLASS: DISCRETE; Manufacturer: PENNENGINEERING; Manufacturer PN: KFH-032-10ET; PART_NUMBER: 769-0005
J5 = PEM-KFH: 10th Part Field: [1]; 9th Part Field: VOUT2; CLASS: DISCRETE; Manufacturer: PENNENGINEERING; Manufacturer PN: KFH-032-10ET; PART_NUMBER: 769-0005
JP1 JP2 = 1X3_A: CONN.,HDR,MALE,1x3,2mm,THT, STR,NO SUBS. ALLOWED; 11th Part Field: OFF; 12th Part Field: RUN1; 9th Part Field: ON; CLASS: IO; Manufacturer: Wurth Elektronik; Manufacturer PN: 62000311121; PART_NUMBER: 250-0639
L1-L6 = IND: INDUCTOR, 0.25uH; CLASS: DISCRETE; Manufacturer: WURTH ELEKTRONIK; Manufacturer PN: 744301025; PART_NUMBER: TMP-3563; Package Size: SMT
R1 R2 = RES: RES.,Metal Foil, 0 mOHM, SM SHUNT,2010; CLASS: DISCRETE; PART_NUMBER: TMP-2449; Package Size: 2010
R3 R5 R7 R8 R11 R12 R14 R16-R18 R27 R29 R39 R40 R46 R49 R67 R68 R77 R80-R83 R89 R105 R110 R113 R116 R119 R122 = RES: RES.,AEC-Q200,0 OHM,1/10W,0603; CLASS: DISCRETE; FPLIST: CR0603N,CR0603L,CR0603M; Manufacturer: VISHAY; Manufacturer PN: CRCW06030000Z0EA; PART_NUMBER: 100-0009; Package Size: 0603; Part Number: VISHAY CRCW06030000Z0EA; Rated Power: 1/10W
R4 R6 R28 R30 R42 R47 R48 R125 = RES: RES.,AEC-Q200,1 OHM,5%,1/10W,0603; CLASS: DISCRETE; FPLIST: CR0603N,CR0603L,CR0603M; Manufacturer: VISHAY; Manufacturer PN: CRCW06031R00JNEA; PART_NUMBER: 100-0271; Package Size: 0603; Part Number: VISHAY CRCW06031R00JNEA; Rated Power: 1/10W; Temperature Coefficient: 200ppm/C; Tolerance: 5%
R9 R10 R31 R32 R51 R52 R74 R75 R85 R90 R92 R93 R96 R97 R101 R102 RB1 RT1 = RES: RES.,AEC-Q200,10k OHMS,1%,1/10W,0603; CLASS: DISCRETE; FPLIST: CR0603N,CR0603L,CR0603M; Manufacturer: VISHAY; Manufacturer PN: CRCW060310K0FKEA; PART_NUMBER: 100-2012; Package Size: 0603; Part Number: VISHAY CRCW060310K0FKEA; Rated Power: 1/10W; Temperature Coefficient: +/-100ppm/C; Tolerance: 1%
R13 R15 R35 R36 R43 R53 R56-R63 R65 R70 R71 R106-R109 R111 R112 R114 R115 R117 R118 R120 R121 R123 R124 = RES: RES., OPTION, 0603; CLASS: DISCRETE; FPLIST: CR0603N,CR0603L,CR0603M; PART_NUMBER: 100-2374; Package Size: 0603
R19 R23 R38 R41 R66 R69 = RES: RES.,715 OHMS,1%,1/10W,0603; CLASS: DISCRETE; FPLIST: CR0603N,CR0603L,CR0603M; Manufacturer: NIC; Manufacturer PN: NRC06F7150TRF; PART_NUMBER: 100-2366; Package Size: 0603; Rated Power: 1/10W; Temperature Coefficient: 100ppm/C; Tolerance: 1%
R20-R22 R24-R26 = RES: RES SMD 2.32K OHM 1% 1/10W 0603; CLASS: DISCRETE; FPLIST: CR0603N,CR0603L,CR0603M; Manufacturer: VISHAY; Manufacturer PN: CRCW06032K32FKEA; PART_NUMBER: TMP-3558; Package Size: 0603 (1608 Metric); Rated Power: 0.1W, 1/10W; Temperature Coefficient: 100ppm/C; Tolerance: 1%
R33 R34 R54 R55 = RES: RES.,Metal Foil, 0 mOHM, SM SHUNT,2010; CLASS: DISCRETE; Manufacturer: TEPRO OF FLORIDA; Manufacturer PN: RN6083; PART_NUMBER: TMP-2449; Package Size: 2010
R37 R50 R64 R76 = RES: RES.,10 OHMS,1%,1/10W,0603; CLASS: DISCRETE; FPLIST: CR0603N,CR0603L,CR0603M; Manufacturer: VISHAY; Manufacturer PN: CRCW060310R0FKEA; PART_NUMBER: 100-2306; Package Size: 0603; Part Number: VISHAY CRCW060310R0FKEA; Rated Power: 1/10W; Temperature Coefficient: 100ppm/C; Tolerance: 1%
R44 = RES: RES.,37.4k OHMS,1%,1/10W,0603; CLASS: DISCRETE; FPLIST: CR0603N,CR0603L,CR0603M; Manufacturer: VISHAY; Manufacturer PN: CRCW060337K4FKEA; PART_NUMBER: TMP-2441; Package Size: 0603; Rated Power: 1/10W; Temperature Coefficient: 100ppm/C; Tolerance: 1%
R45 = RES: RES., OPTION, 0603; CLASS: DISCRETE; FPLIST: CR0603N,CR0603L,CR0603M; PART_NUMBER: 100-2374; Package Size: 0603; Part Number: OPTION
R72 R73 = RES: RES.,AEC-Q200,39.2k OHMS,1%,1/10W,0603; CLASS: DISCRETE; FPLIST: CR0603N,CR0603L,CR0603M; Manufacturer: VISHAY; Manufacturer PN: CRCW060339K2FKEA; PART_NUMBER: 100-2741; Package Size: 0603; Rated Power: 1/10W; Temperature Coefficient: 100ppm/C; Tolerance: 1%
R78 R79 R127 = RES: RES.,AEC-Q200,100k OHMS,1%,1/10W,0603; CLASS: DISCRETE; FPLIST: CR0603N,CR0603L,CR0603M; Manufacturer: VISHAY; Manufacturer PN: CRCW0603100KFKEA; PART_NUMBER: 100-0343; Package Size: 0603; Part Number: VISHAY CRCW0603100KFKEA; Rated Power: 1/10W; Temperature Coefficient: +/-100ppm; Tolerance: 1%
R94 R95 R99 R100 R103 R104 = RES: RES.,24.9k OHMS,1%,1/10W,0603; CLASS: DISCRETE; FPLIST: CR0603N,CR0603L,CR0603M; Manufacturer: VISHAY; Manufacturer PN: CRCW060324K9FKEA; PART_NUMBER: 100-0037; Package Size: 0603; Part Number: VISHAY CRCW060324K9FKEA; Rated Power: 1/10W; Temperature Coefficient: 100ppm/C; Tolerance: 1%
RB2 = RES: RES.,AEC-Q200,10k OHMS,1%,1/10W,0603; CLASS: DISCRETE; FPLIST: CR0603N,CR0603L,CR0603M; PART_NUMBER: 100-2012; Package Size: 0603; Part Number: VISHAY CRCW060310K0FKEA
RITH1 = RES: RES.,4.99k OHMS,1%,1/10W,0603; CLASS: DISCRETE; FPLIST: CR0603N,CR0603L,CR0603M; Manufacturer: VISHAY; Manufacturer PN: CRCW06034K99FKEA; PART_NUMBER: TMP-3061; Package Size: 0603; Part Number: VISHAY CRCW06033K01FKEA; Rated Power: 1/10W; Temperature Coefficient: +/-25PPM; Tolerance: 1%
RITH2 = RES: RES.,AEC-Q200,7.5k OHMS,1%,1/10W,0603; CLASS: DISCRETE; FPLIST: CR0603N,CR0603L,CR0603M; PART_NUMBER: 100-1007; Package Size: 0603
RT2 = RES: RES.,20k OHMS,1%,1/10W,0603; CLASS: DISCRETE; FPLIST: CR0603N,CR0603L,CR0603M; PART_NUMBER: 100-2117; Package Size: 0603; Part Number: VISHAY CRCW060320K0FKEA
TP6-TP11 = E-100SMT_0: NONE; Part Number: NONE
U1-U6 = FARCHILD-FDMF5820DC: IC, SMAT POWER STAGE MODULE; CLASS: IC; Manufacturer: FAIRCHILD; PART_NUMBER: TMP-3559; Package Size: 5.00mmx5.00mm; Part Number: FAIRCHILD FDMF5820DC
U7 = LTC7852-RHE_0: IC,DUALOUTPUT 6-PHASE CONTROLLER,GQFN-48 (5x6); CLASS: IC; Manufacturer: ANALOG DEVICES; Manufacturer PN: LTC7852ERHE#PBF; PART_NUMBER: TMP-3566; Package Size: 48GQFN-5mmX6mm; Package Type: GQFN-48 (5mmX6mm)
XJP1-XJP4 = SHUNT_2MM: CONN.,SHUNT,FEMALE,2 POS,2mm; CLASS: IO; Manufacturer: Wurth Elektronik; Manufacturer PN: 60800213421; PART_NUMBER: 250-0485
C40 C46 C47 = CAP: CAP.,1uF,X7R,50V,10%,0805; CLASS: DISCRETE; Dielectric Type: X7R; FPLIST: CC0805N,CC0805L,CC0805M; Manufacturer: AVX; Manufacturer PN: 08055C105KAT2A; PART_NUMBER: 150-2373; Package Size: 0805; Rated Voltage: 50V; Tolerance: 10%
C42 = CAP: CAP.,22uF,X5R,6.3V,20%,0805; CLASS: DISCRETE; Dielectric Type: X5R; FPLIST: CC0805N,CC0805L,CC0805M; Manufacturer: MURATA; Manufacturer PN: GRM21BR60J226ME39L; PART_NUMBER: 150-0296; Package Size: 0805; Rated Voltage: 6.3V; Tolerance: 20%
C43 = CAP: CAP.,10uF,X5R,6.3V,10%,0805; CLASS: DISCRETE; Dielectric Type: X5R; FPLIST: CC0805N,CC0805L,CC0805M; Manufacturer: AVX; Manufacturer PN: 08056D106KAT2A; PART_NUMBER: 150-0079; Package Size: 0805; Rated Voltage: 6.3V; Tolerance: 10%
C48 C50 = RES: RES.,AEC-Q200,100 OHMS,1%,1/8W ,0805; CLASS: DISCRETE; FPLIST: CR0805N,CR0805L,CR0805M; Manufacturer: VISHAY; Manufacturer PN: CRCW0805100RFKEA; PART_NUMBER: 100-0099; Package Size: 0805; Rated Power: 1/8W; Temperature Coefficient: 100ppm; Tolerance: 1%
C49 C51 = CAP: CAP.,47uF,X5R,6.3V,20%,0805; CLASS: DISCRETE; Dielectric Type: X5R; FPLIST: CC0805N,CC0805L,CC0805M; Manufacturer: TAIYO YUDEN; Manufacturer PN: JMK212BBJ476MG-T; PART_NUMBER: 150-0140; Package Size: 0805; Rated Voltage: 6.3V; Tolerance: 20%
C67 = CAP: CAP.,220pF,X7R,50V,5%,0603; CLASS: DISCRETE; Dielectric Type: X7R; Manufacturer: AVX; Manufacturer PN: 06035C221JAT2A; PART_NUMBER: 150-0040; Package Size: 0603; Part Number: AVX 06035C221JAT2A; Rated Voltage: 50V; Tolerance: 5%
CIN16-CIN27 = CAP: CAP., OPTION, 1210; CLASS: DISCRETE; FPLIST: CC1210N,CC1210L,CC1210M; PART_NUMBER: 150-3035; Package Size: 1210; Package Type: SMD
COUT2 COUT4 COUT6 COUT8 COUT10 COUT12 = CAP: CAP., OPTION, 1206; CLASS: DISCRETE; FPLIST: CC1206N,CC1206L,CC1206M; PART_NUMBER: 150-3160; Package Size: 1206; Package Type: SMD
COUT31-COUT48 = CAP_P: CAP., OPTION, 7343; CLASS: DISCRETE; FPLIST: CAPMP7343N,CAPMP7343L,CAPMP7343M; PART_NUMBER: 150-0067; Package Size: 7343; Package Type: SMD
D1 = DIODE_SCHOTTKY_A_0: DIODE, SCHOTTKY BARRIER RECTIFIER, 40V 500mA, SOD-323; CLASS: DISCRETE; Manufacturer: NXP; Manufacturer PN: PMEG4005AEA,115; PART_NUMBER: TMP-2448; Package Size: SOD-323; Rated Voltage or Zener Voltage: 40V
E18 = TURRET_A: TEST POINT,TURRET,0.094",MTG. HOLE; 9th Part Field: PULSE GEN 1; CLASS: IO; Manufacturer: MILL-MAX; Manufacturer PN: 2501-2-00-80-00-00-07-0; PART_FIELD_01: <PART_FIELD_01>; PART_NUMBER: 260-0003
E19 = TURRET_A: TEST POINT,TURRET,0.094",MTG. HOLE; 4th Part Field: 5VBIAS; 9th Part Field: 5.0V / 500mA; CLASS: IO; Manufacturer: MILL-MAX; Manufacturer PN: 2501-2-00-80-00-00-07-0; PART_FIELD_01: <PART_FIELD_01>; PART_NUMBER: 260-0003
E20 E29 = TURRET_A: TEST POINT,TURRET,0.094",MTG. HOLE; 4th Part Field: GND; 9th Part Field: 5.0V / 500mA; CLASS: IO; Manufacturer: MILL-MAX; Manufacturer PN: 2501-2-00-80-00-00-07-0; PART_FIELD_01: <PART_FIELD_01>; PART_NUMBER: 260-0003
E21 E25 = TURRET_A: TEST POINT,TURRET,0.094",MTG. HOLE; 9th Part Field: GND; CLASS: IO; Manufacturer: MILL-MAX; Manufacturer PN: 2501-2-00-80-00-00-07-0; PART_FIELD_01: <PART_FIELD_01>; PART_NUMBER: 260-0003
E22 = TURRET_A: TEST POINT,TURRET,0.094",MTG. HOLE; 9th Part Field: ISTEP1+; CLASS: IO; Manufacturer: MILL-MAX; Manufacturer PN: 2501-2-00-80-00-00-07-0; PART_FIELD_01: <PART_FIELD_01>; PART_NUMBER: 260-0003
E23 = TURRET_A: TEST POINT,TURRET,0.094",MTG. HOLE; 9th Part Field: ISTEP1-; CLASS: IO; Manufacturer: MILL-MAX; Manufacturer PN: 2501-2-00-80-00-00-07-0; PART_FIELD_01: <PART_FIELD_01>; PART_NUMBER: 260-0003
E24 = TURRET_A: TEST POINT,TURRET,0.094",MTG. HOLE; 9th Part Field: PULSE GEN 2; CLASS: IO; Manufacturer: MILL-MAX; Manufacturer PN: 2501-2-00-80-00-00-07-0; PART_FIELD_01: <PART_FIELD_01>; PART_NUMBER: 260-0003
E26 = TURRET_A: TEST POINT,TURRET,0.094",MTG. HOLE; 9th Part Field: ISTEP2+; CLASS: IO; Manufacturer: MILL-MAX; Manufacturer PN: 2501-2-00-80-00-00-07-0; PART_FIELD_01: <PART_FIELD_01>; PART_NUMBER: 260-0003
E27 = TURRET_A: TEST POINT,TURRET,0.094",MTG. HOLE; 9th Part Field: ISTEP2-; CLASS: IO; Manufacturer: MILL-MAX; Manufacturer PN: 2501-2-00-80-00-00-07-0; PART_FIELD_01: <PART_FIELD_01>; PART_NUMBER: 260-0003
E28 = TURRET_A: TEST POINT,TURRET,0.094",MTG. HOLE; 10th Part Field: 3.3V/50mA; 4th Part Field: 3.3VAUX; 9th Part Field: 3.3V/50mA; CLASS: IO; Manufacturer: MILL-MAX; Manufacturer PN: 2501-2-00-80-00-00-07-0; PART_FIELD_01: <PART_FIELD_01>; PART_NUMBER: 260-0003
J7 = BNC_50_OHM_112404_B: CONN.,RF, BNC,RCPT JACK,5-PIN,STR, THT,50 Ohms; 10th Part Field: 5% DUTY CYCLE MAX.; 9th Part Field: VOUT1; CLASS: IO; Manufacturer: AMPHENOL RF; Manufacturer PN: 112404; PART_NUMBER: 250-0427
J8 = BNC_50_OHM_112404_B: CONN.,RF, BNC,RCPT JACK,5-PIN,STR, THT,50 Ohms; 10th Part Field: 5% DUTY CYCLE MAX.; 9th Part Field: VOUT2; CLASS: IO; Manufacturer: AMPHENOL RF; Manufacturer PN: 112404; PART_NUMBER: 250-0427
JP3 = 1X3_A: CONN.,HDR,MALE,1x3,2mm,STR, THT,NO SUBS. ALLOWED; 11th Part Field: OFF; 12th Part Field: 5VBIAS; 9th Part Field: ON; CLASS: IO; Manufacturer: Wurth Elektronik; Manufacturer PN: 62000311121; PART_NUMBER: 250-0639
JP4 = 1X3_A: CONN.,HDR,MALE,1x3,2mm,STR, THT,NO SUBS. ALLOWED; 11th Part Field: OFF; 12th Part Field: 3.3VAUX; 9th Part Field: ON; CLASS: IO; Manufacturer: Wurth Elektronik; Manufacturer PN: 62000311121; PART_NUMBER: 250-0639
L7 = IND_ALT: IND,15uH,HIGH CURRENT LOW PROFILE SMD; CLASS: DISCRETE; Manufacturer: Eaton; Manufacturer PN: MP14020V2-150-R; PART_NUMBER: TMP-3562; Package Size: 4.40mmX4.20mmX1.80mm; Tolerance: 20%
Q1 = 3P_N-CH_TYPE2A_2: XSTR.,N-CH, LOGIC LEVEL PWR. TRENCH MOSFET, 30V,80A, TO-263AB; CLASS: DISCRETE; Manufacturer: FAIRCHILD SEMI; PART_NUMBER: TMP-2409; Rated Voltage: 80V
Q2 = 3P_N-CH_TYPE2A_3: XSTR.,N-CH, LOGIC LEVEL PWR. TRENCH MOSFET, 30V,80A, TO-263AB; CLASS: DISCRETE; Manufacturer: FAIRCHILD SEMI; PART_NUMBER: TMP-2409; Rated Voltage: 80V
R84 = RES: RES.,AEC-Q200,0 OHM,1/4W,1206; CLASS: DISCRETE; FPLIST: CR1206N,CR1206L,CR1206M; Manufacturer: VISHAY; Manufacturer PN: CRCW12060000Z0EA; PART_NUMBER: 100-0200; Package Size: 1206; Part Number: VISHAY CRCW12060000Z0EA; Rated Power: 1/4W
R86 = RES: RES.,105k OHMS,1%,1/10W,0603; CLASS: DISCRETE; FPLIST: CR0603N,CR0603L,CR0603M; Manufacturer: VISHAY; Manufacturer PN: CRCW0603105KFKEA; PART_NUMBER: 100-0366; Package Size: 0603; Rated Power: 1/10W; Temperature Coefficient: 100ppm/C; Tolerance: 1%
R87 R91 = RES: RES.,SENSE,0.002 OHM,1%,1W,2512; CLASS: DISCRETE; FPLIST: CR2512N,CR2512L,CR2512M; Manufacturer: VISHAY; Manufacturer PN: WSL25122L000FEA; PART_NUMBER: 100-0062; Package Size: 2512; Rated Power: 1W; Temperature Coefficient: 275ppm/C; Tolerance: 1%
R88 = RES: RES.,20k OHMS,1%,1/10W,0603; CLASS: DISCRETE; FPLIST: CR0603N,CR0603L,CR0603M; Manufacturer: VISHAY; Manufacturer PN: CRCW060320K0FKEA; PART_NUMBER: 100-2117; Package Size: 0603; Part Number: VISHAY CRCW060320K0FKEA; Rated Power: 1/10W; Temperature Coefficient: +/-100PPM; Tolerance: 1%
R126 = RES: RES.,AEC-Q200,1M OHM,1%,1/10W,0603; CLASS: DISCRETE; Manufacturer: VISHAY; Manufacturer PN: CRCW06031M00FKEA; PART_NUMBER: 100-0335; Package Size: 0603; Part Number: VISHAY CRCW06031M00FKEA; Rated Power: 1/10W; Temperature Coefficient: 100ppm; Tolerance: 1%
R128 = RES: RES.,AEC-Q200,162k OHMS,1%,1/10W,0603; CLASS: DISCRETE; Manufacturer: VISHAY; Manufacturer PN: CRCW0603162KFKEA; PART_NUMBER: 100-2381; Package Size: 0603; Part Number: VISHAY CRCW0603162KFKEA; Rated Power: 1/10W; Temperature Coefficient: 100ppm/C; Tolerance: 1%
R129 = RES: RES.,AEC-Q200,0 OHM,1/4W,1206; CLASS: DISCRETE; Manufacturer: VISHAY; Manufacturer PN: CRCW12060000Z0EA; PART_NUMBER: 100-0200; Package Size: 1206; Part Number: VISHAY CRCW12060000Z0EA; Rated Power: 1/4W
U8 = LT3502-DC-8: IC,1.1MHz/2.2MHz, 500mA STEP-DOWN REGULATOR; CLASS: IC; Manufacturer: ANALOG DEVICES; PART_NUMBER: TMP-3561; Package Type: 8-PIN DC8
U9 = LT3010-MS8E-X_3: IC,LDO uPWR LINEAR REG.,MSOP-8; CLASS: IC; Manufacturer: LINEAR TECH.; Manufacturer PN: LT3010EMS8E#PBF; PART_NUMBER: LT3010EMS8E#PBF; Package Size: 20-TSSOP; Package Type: MSOP-8
JLRE1-JLRE6 = Lug_Ring: RING, LUG, CRIMP,#10,NON-INSULATED,SOLDERLESS TERMINALS; Manufacturer: KEYSTONE; Manufacturer PN: 8205; PART_NUMBER: 769-0010; Part Number: KEYSTONE 8205
JNE1-JNE12 = NUT: NUT,HEX,#10-32,BRASS; Manufacturer: PENCOM; Manufacturer PN: NU1132; PART_NUMBER: 761-0013; Part Number: PENCOM NU1132
JWE1-JWE6 = Washer: WASHER,#10,LOCK,EXT,TIN FINISH; Manufacturer: PENCOM; Manufacturer PN: WA4526; PART_NUMBER: 762-0021; Part Number: PENCOM WA4526
LB1 = BLANK_LABEL: LABEL SPEC, DEMO BOARD SERIAL NUMBER; Manufacturer: BRADY; Manufacturer PN: THT-96-717-10; PART_NUMBER: 895-0154
MP1-MP4 = MP-PINNED: STANDOFF,NYLON,SNAP-ON,0.625"; CLASS: DISCRETE; Manufacturer: KEYSTONE; Manufacturer PN: 8834; PART_NUMBER: 763-0013
PCB1 = BLANK_PCB_PART: BOM Notes: REV04; CLASS: DISCRETE; Manufacturer: PHASE 3 TECHNOLOGIES INC.; Manufacturer PN: 600-DC2631A; PART_NUMBER: TMP-3564
STNCL1 STNCL2 = BLANK_STENCIL_PART: TOOL, STENCIL, DC2631A; BOM Notes: REV04; CLASS: DISCRETE; Manufacturer: LINEAR TECH.; Manufacturer PN: 830-DC2631A; PART_NUMBER: TMP-3565
X1-X8 = CON1: DO NOT STUFF; Part Number: PADS ONLY

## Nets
3.3V_VDD: C7.1 R108.1 U7.39(VDD)
3.3VAUX: C69.2 E28.1 R109.2 R129.2
3.3VPLP: C60.1 C61.1 C62.1 C63.1 C64.1 C65.1 R106.2 R108.2 R109.1 R111.2 R114.2 R117.1 R120.1 R123.1
5VBIAS: C5.2 C6.2 C24.2 C25.2 C36.2 C37.2 C43.1 E19.1 R4.2 R6.2 R28.2 R30.2 R42.1 R47.2 R48.2 R84.2 R125.2 U1.29(PVCC) U2.29(PVCC) U3.29(PVCC) U4.29(PVCC) U5.29(PVCC) U6.29(PVCC)
AGND: C7.2 C28.2 C29.1 C30.1 C31.1 CITH1.2 CITH2.2 CITHP1.2 CITHP2.2 R44.1 R45.1 R60.1 R61.1 U7.48(GND) U7.49(GND) U7.50(AGND) U7.51(AGND) U7.52(AGND) U7.53(AGND)
GND: C1.1 C2.1 C5.1 C6.1 C18.1 C19.1 C24.1 C25.1 C32.1 C33.1 C36.1 C37.1 C38.2 C39.2 C40.2 C42.2 C43.2 C45.2 C46.2 C47.2 C48.2 C49.2 C50.2 C51.2 C54.2 C55.2 C56.2 C57.2 C58.2 C59.2 C60.2 C61.2 C62.2 C63.2 C64.2 C65.2 C66.1 C68.1 C69.1 CIN1.2 CIN2.2 CIN3.2 CIN4.2 CIN5.2 CIN6.2 CIN7.2 CIN8.2 CIN9.2 CIN10.2 CIN11.2 CIN12.2 CIN13.2 CIN14.2 CIN15.2 CIN16.2 CIN17.2 CIN18.2 CIN19.2 CIN20.2 CIN21.2 CIN22.2 CIN23.2 CIN24.2 CIN25.2 CIN26.2 CIN27.2 COUT1.2 COUT2.2 COUT3.2 COUT4.2 COUT5.2 COUT6.2 COUT7.2 COUT8.2 COUT9.2 COUT10.2 COUT11.2 COUT12.2 COUT13.2 COUT14.2 COUT15.2 COUT16.2 COUT17.2 COUT18.2 COUT19.2 COUT20.2 COUT21.2 COUT22.2 COUT23.2 COUT24.2 COUT25.2 COUT26.2 COUT27.2 COUT28.2 COUT29.2 COUT30.2 COUT31.2 COUT32.2 COUT33.2 COUT34.2 COUT35.2 COUT36.2 COUT37.2 COUT38.2 COUT39.2 COUT40.2 COUT41.2 COUT42.2 COUT43.2 COUT44.2 COUT45.2 COUT46.2 COUT47.2 COUT48.2 E2.1 E20.1 E21.1 E23.1 E25.1 E27.1 E29.1 J2.1 J4.1 J6.1 J7.2 J7.3 J7.4 J7.5 J8.2 J8.3 J8.4 J8.5 JP1.3 JP2.3 JP3.3 JP4.3 R37.1 R64.1 R74.1 R75.1 R85.2 R87.2 R88.2 R90.2 R91.2 R94.1 R95.1 R99.1 R100.1 R103.1 R104.1 R107.2 R112.2 R115.2 R118.2 R121.2 R124.2 R127.2 U1.4(AGND) U1.12(PGND) U1.13(PGND) U1.14(PGND) U1.15(PGND) U1.28(PGND) U1.32(AGND) U2.4(AGND) U2.12(PGND) U2.13(PGND) U2.14(PGND) U2.15(PGND) U2.28(PGND) U2.32(AGND) U3.4(AGND) U3.12(PGND) U3.13(PGND) U3.14(PGND) U3.15(PGND) U3.28(PGND) U3.32(AGND) U4.4(AGND) U4.12(PGND) U4.13(PGND) U4.14(PGND) U4.15(PGND) U4.28(PGND) U4.32(AGND) U5.4(AGND) U5.12(PGND) U5.13(PGND) U5.14(PGND) U5.15(PGND) U5.28(PGND) U5.32(AGND) U6.4(AGND) U6.12(PGND) U6.13(PGND) U6.14(PGND) U6.15(PGND) U6.28(PGND) U6.32(AGND) U8.5(GND) U8.9(GND) U9.3(NC) U9.4(GND) U9.6(NC) U9.7(NC) U9.9(GND)
V1P5: C26.2 C27.1 C28.1 C52.2 C53.1 E17.1 U7.18(V1P5)
VCC: C29.2 R42.2 R43.2 R53.2 R57.2 R59.2 R62.2 R63.2 R65.2 R70.2 R71.2 R78.1 R79.1 U7.20(VCC)
VIN: C40.1 CIN1.1 CIN2.1 CIN3.1 CIN4.1 CIN5.1 CIN6.1 CIN7.1 CIN8.1 CIN9.1 CIN10.1 CIN11.1 CIN12.1 CIN13.1 CIN14.1 CIN15.1 CIN16.1 CIN17.1 CIN18.1 CIN19.1 CIN20.1 CIN21.1 CIN22.1 CIN23.1 CIN24.1 CIN25.1 CIN26.1 CIN27.1 E1.1 J1.1 R72.2 R73.2 R89.1 U1.8(VIN) U1.9(VIN) U1.10(VIN) U1.11(VIN) U2.8(VIN) U2.9(VIN) U2.10(VIN) U2.11(VIN) U3.8(VIN) U3.9(VIN) U3.10(VIN) U3.11(VIN) U4.8(VIN) U4.9(VIN) U4.10(VIN) U4.11(VIN) U5.8(VIN) U5.9(VIN) U5.10(VIN) U5.11(VIN) U6.8(VIN) U6.9(VIN) U6.10(VIN) U6.11(VIN) U8.1(VIN)
CLKOUT: E9.1 U7.40(CLKOUT)
IMON1: C27.2 C52.1 E15.1 U7.19(IMON1)
IMON2: C26.1 C53.2 E16.1 U7.17(IMON2)
ITH1: CITHP1.1 R77.1 RITH1.2 U7.27(ITH1)
ITH2: CITHP2.1 R77.2 RITH2.2 U7.12(ITH2)
PGOOD1: E13.1 R78.2 U7.29(PGOOD1)
PGOOD2: E14.1 R79.2 U7.10(PGOOD2)
PLLIN: E10.1 U7.47(PLLIN)
PWM1: R16.1 U1.1(PWM)
PWM2: R12.1 U2.1(PWM)
PWM3: R8.1 U3.1(PWM)
PWM4: R7.1 U4.1(PWM)
PWM5: R11.1 U5.1(PWM)
PWM6: R14.1 U6.1(PWM)
RUN1: C38.1 E6.1 JP1.2 R72.1 R74.2 R82.1 U7.24(RUN1)
RUN2: C39.1 E7.1 JP2.2 R73.1 R75.2 R82.2 U7.15(RUN2)
SNSAVG1: C17.1 R26.2 R59.1 U7.32(SNSAVG1)
SNSAVG2: C13.1 R24.2 R62.1 U7.35(SNSAVG2)
SNSAVG3: C9.1 R21.2 R63.1 U7.38(SNSAVG3)
SNSAVG4: C8.1 R20.2 R65.1 U7.1(SNSAVG4)
SNSAVG5: C12.1 R22.2 R70.1 U7.4(SNSAVG5)
SNSAVG6: C16.1 R25.2 R71.1 U7.7(SNSAVG6)
SNSN1: C21.2 R26.1 R67.2 U7.30(SNSN1)
SNSN2: C15.2 R24.1 R39.2 U7.33(SNSN2)
SNSN3: C11.2 R17.2 R21.1 U7.36(SNSN3)
SNSN4: C10.2 R18.2 R20.1 U7.3(SNSN4)
SNSN5: C14.2 R22.1 R40.2 U7.6(SNSN5)
SNSN6: C20.2 R25.1 R68.2 U7.9(SNSN6)
SNSP1: C17.2 C21.1 R66.2 U7.31(SNSP1)
SNSP2: C13.2 C15.1 R38.2 U7.34(SNSP2)
SNSP3: C9.2 C11.1 R23.2 U7.37(SNSP3)
SNSP4: C8.2 C10.1 R19.2 U7.2(SNSP4)
SNSP5: C12.2 C14.1 R41.2 U7.5(SNSP5)
SNSP6: C16.2 C20.1 R69.2 U7.8(SNSP6)
SS1: C30.2 E11.1 R80.1 U7.28(SS1)
SS2: C31.2 E12.1 R80.2 U7.11(SS2)
VO2PH4: COUT7.1 COUT8.1 COUT22.1 COUT23.1 COUT24.1 COUT40.1 COUT41.1 COUT42.1 L4.2 R1.1 R2.1 R18.1 R33.1 R34.1
VO2PH5: COUT9.1 COUT10.1 COUT25.1 COUT26.1 COUT27.1 COUT46.1 COUT47.1 COUT48.1 L5.2 R33.2 R34.2 R40.1 R54.1 R55.1
VOS1+: CFF1.1 E3.1 R50.2 RT1.2
VOS1-: E4.1 R37.2 R83.1 RB1.1 U7.26(VOSNS1-)
VOS2+: CFF2.2 E5.1 R76.2 RT2.2
VOS2-: E8.1 R64.2 R83.2 RB2.1 U7.13(VOSNS2-)
VOSNS1+: CFF1.2 R81.1 RB1.2 RT1.1 U7.25(VOSNS1+)
VOSNS2+: CFF2.1 R81.2 RB2.2 RT2.1 U7.14(VOSNS2+)
VOUT1: C46.1 C48.1 C49.1 COUT1.1 COUT2.1 COUT3.1 COUT4.1 COUT5.1 COUT6.1 COUT13.1 COUT14.1 COUT15.1 COUT16.1 COUT17.1 COUT18.1 COUT19.1 COUT20.1 COUT21.1 COUT31.1 COUT32.1 COUT33.1 COUT34.1 COUT35.1 COUT36.1 COUT43.1 COUT44.1 COUT45.1 J3.1 J7.1 L1.2 L2.2 L3.2 Q1.3(S) R1.2 R2.2 R17.1 R39.1 R50.1 R67.1
VOUT2: C47.1 C50.1 C51.1 COUT11.1 COUT12.1 COUT28.1 COUT29.1 COUT30.1 COUT37.1 COUT38.1 COUT39.1 J5.1 J8.1 L6.2 Q2.3(S) R54.2 R55.2 R68.1 R76.1
N835795: L3.1 R23.1 U3.16(SW) U3.17(SW) U3.18(SW) U3.19(SW) U3.20(SW) U3.21(SW) U3.22(SW) U3.23(SW) U3.24(SW) U3.25(SW) U3.26(SW)
N835907: R53.1 R60.2 U7.16(ILIM2)
N836021: R43.1 R45.2 U7.23(ILIM1)
N836193: R57.1 R61.2 U7.21(PHCFG)
N836333: CITH2.1 RITH2.1
N836553: CITH1.1 RITH1.1
N836597: R44.2 U7.22(FREQ)
N837857: L2.1 R38.1 U2.16(SW) U2.17(SW) U2.18(SW) U2.19(SW) U2.20(SW) U2.21(SW) U2.22(SW) U2.23(SW) U2.24(SW) U2.25(SW) U2.26(SW)
N838107: L1.1 R66.1 U1.16(SW) U1.17(SW) U1.18(SW) U1.19(SW) U1.20(SW) U1.21(SW) U1.22(SW) U1.23(SW) U1.24(SW) U1.25(SW) U1.26(SW)
N838849: R8.2 U7.43(PWM3)
N839075: R16.2 U7.41(PWM1)
N839097: R12.2 U7.42(PWM2)
N839217: R7.2 U7.44(PWM4)
N839237: R14.2 U7.46(PWM6)
N839251: R11.2 U7.45(PWM5)
N840321: L4.1 R19.1 U4.16(SW) U4.17(SW) U4.18(SW) U4.19(SW) U4.20(SW) U4.21(SW) U4.22(SW) U4.23(SW) U4.24(SW) U4.25(SW) U4.26(SW)
N841027: L5.1 R41.1 U5.16(SW) U5.17(SW) U5.18(SW) U5.19(SW) U5.20(SW) U5.21(SW) U5.22(SW) U5.23(SW) U5.24(SW) U5.25(SW) U5.26(SW)
N842433: L6.1 R69.1 U6.16(SW) U6.17(SW) U6.18(SW) U6.19(SW) U6.20(SW) U6.21(SW) U6.22(SW) U6.23(SW) U6.24(SW) U6.25(SW) U6.26(SW)
N845375: E24.1 Q2.1(G) R90.1
N845459: E26.1 Q2.2(D) R91.1
N845993: E18.1 Q1.1(G) R85.1
N846075: E22.1 Q1.2(D) R87.1
N846207: C44.2 R86.2 R88.1 U8.3(FB)
N846273: C45.1 JP3.2 U8.4(~{SHDN})
N846367: C41.1 D1.1(C) L7.1 U8.8(SW)
N846371: C41.2 U8.7(BOOST)
N846379: D1.2(A) U8.6(DA)
N846417: C42.1 C44.1 L7.2 R84.1 R86.1 U8.2(BD)
N846649: JP3.1 R89.2
N1311356: C1.2 R4.1 R93.1 R113.2 U3.3(VCC)
N1311458: R9.2 R115.1 TP8.1(A) U3.31(EN/FAULT#)
N1311474: C54.1 R15.2 R95.2 U3.30(TMON)
N1311482: R3.1 U3.5(BOOT)
N1311498: R93.2 U3.2(ZCD#)
N1311542: C4.1 R3.2
N1311584: C4.2 U3.7(PHASE)
N1326176: R31.2 R112.1 TP7.1(A) U2.31(EN/FAULT#)
N1326200: C18.2 R28.1 R97.1 R110.2 U2.3(VCC)
N1326318: R27.1 U2.5(BOOT)
N1326326: C57.1 R36.2 R100.2 U2.30(TMON)
N1326338: R97.2 U2.2(ZCD#)
N1326382: C22.1 R27.2
N1326424: C22.2 U2.7(PHASE)
N1328113: C32.2 R47.1 R102.1 R105.2 U1.3(VCC)
N1328227: R46.1 U1.5(BOOT)
N1328247: R102.2 U1.2(ZCD#)
N1328275: C34.1 R46.2
N1328329: C34.2 U1.7(PHASE)
N1328661: C59.1 R58.2 R104.2 U1.30(TMON)
N1329656: R51.2 R107.1 TP6.1(A) U1.31(EN/FAULT#)
N1339701: R10.2 R124.1 TP11.1(A) U4.31(EN/FAULT#)
N1339725: C2.2 R6.1 R92.1 R122.2 U4.3(VCC)
N1339843: C55.1 R13.2 R94.2 U4.30(TMON)
N1339847: R5.1 U4.5(BOOT)
N1339863: R92.2 U4.2(ZCD#)
N1339907: C3.1 R5.2
N1339949: C3.2 U4.7(PHASE)
N1347653: R32.2 R121.1 TP10.1(A) U5.31(EN/FAULT#)
N1347677: C19.2 R30.1 R96.1 R119.2 U5.3(VCC)
N1347795: C56.1 R35.2 R99.2 U5.30(TMON)
N1347799: R29.1 U5.5(BOOT)
N1347815: R96.2 U5.2(ZCD#)
N1347859: C23.1 R29.2
N1347897: C23.2 U5.7(PHASE)
N1349873: R52.2 R118.1 TP9.1(A) U6.31(EN/FAULT#)
N1349889: C33.2 R48.1 R101.1 R116.2 U6.3(VCC)
N1350007: R49.1 U6.5(BOOT)
N1350023: R101.2 U6.2(ZCD#)
N1350067: C35.1 R49.2
N1350105: C35.2 U6.7(PHASE)
N1350433: C58.1 R56.2 R103.2 U6.30(TMON)
N1841673: R51.1 R58.1 R105.1 R106.1
N1847688: R31.1 R36.1 R110.1 R111.1
N1850599: R9.1 R15.1 R113.1 R114.1
N1851456: R52.1 R56.1 R116.1 R117.2
N1855651: R32.1 R35.1 R119.1 R120.2
N1858714: R10.1 R13.1 R122.1 R123.2
N1860718: C66.2 R125.1 R126.1 U9.8(IN)
N1861437: JP4.1 R126.2
N1861459: JP4.2 U9.5(~{SHDN})
N1864702: C67.1 C68.2 R128.1 R129.1 U9.1(OUT)
N1864706: C67.2 R127.1 R128.2 U9.2(SENSE/ADJ)

Not connected (* = marked no-connect by the designer): JP1 1; JP2 1; MP1 1; MP2 1; MP3 1; MP4 1; U1 6(NC) 27(GL) 33(GL); U2 6(NC) 27(GL) 33(GL); U3 6(NC) 27(GL) 33(GL); U4 6(NC) 27(GL) 33(GL); U5 6(NC) 27(GL) 33(GL); U6 6(NC) 27(GL) 33(GL); X1 1; X2 1; X3 1; X4 1; X5 1; X6 1; X7 1; X8 1

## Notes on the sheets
sheet 1
- HARDWARE
- PCA ADDITIONAL PARTS
- STANDOFFS
- TOOLING HOLES
- NON-PLATED HOLES
sheet 2
- REVISION HISTORY
- ECO
- REV
- DESCRIPTION
- DATE
- APPROVED
- 4
- PROD
- 06/26/18
- M. S.
- -B
- [1]
- [1]
- [1]
- [1]
- [1]
- [1]
- Fsw = 400kHz
- For conventional DCR sense
- -B
- [1]
- ASSY
- VOUT1
- VOUT2
- RITH1
- CITH1
- RITH2
- CITH2
- RT2
- RB2
- -A
- 1.0V / 100A
- 1.5V / 100A
- 4.99k
- 3.3nF
- 7.50k
- 2.2nF
- 20k
- 10k
- -B
- 1.0V / 200A
- 2.49k
- 5.6nF
- OPT
- OPT
- OPT
- OPT
- [2]    RESISTORS SHALL BE INSTALLED AT LOCATIONS C48 AND C50.
sheet 3
- DYNAMIC LOAD CIRCUITS
- BIAS SUPPLY FOR DrMOS and LTC7852
- [2]
- 2mV / Amp
- 5% DUTY CYCLE MAX.
- NOTE:
- If external 5V bias is applied, remove R84 and place the 5VBIAS jumper in the OFF position.
- [2]
- Next, connect the external supply to the 5VBIAS turret and turn-on supply,
- Do not hot plug.
- 2mV / Amp
- 5% DUTY CYCLE MAX.
- 3.3V AUXILIARY SUPPLY
- NOTE: PRE-LOAD RESISTORS ARE STUFFED AT C48 AND C50.
- NOTE:
- If external 3.3V bias is applied, remove R129 and place the 3.3VAUX jumper in the OFF position.
- Next, connect the external supply to the 3.3VAUX turret and turn-on supply,
- Do not hot plug.
